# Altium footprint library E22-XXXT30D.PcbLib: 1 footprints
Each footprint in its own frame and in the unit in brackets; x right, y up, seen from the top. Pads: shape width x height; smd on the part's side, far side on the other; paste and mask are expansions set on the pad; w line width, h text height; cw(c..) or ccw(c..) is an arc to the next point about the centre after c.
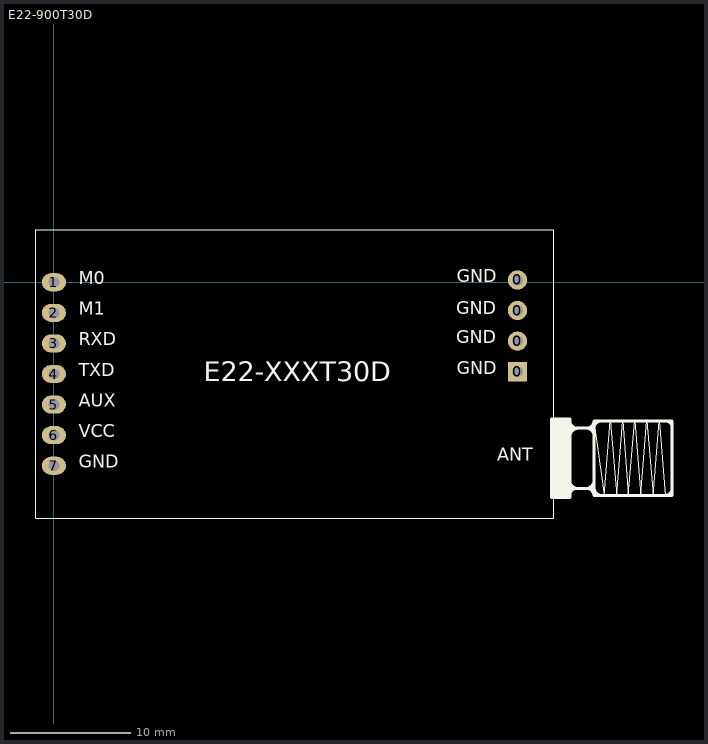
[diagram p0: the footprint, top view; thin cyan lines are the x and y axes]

## E22-900T30D [mm] "43MM*24mm-D//SMA长度12.5mm"
pads (11):
  rect 1.6x1.6 hole 0.9: 0(38.5,-7.43)
  round 1.6 hole 0.9: 0(38.5,-4.89) 0(38.5,-2.35) 0(38.5,0.19)
  oval 2x1.5 hole 0.9: 1(0,0) 2(0,-2.54) 3(0,-5.08) 4(0,-7.62) 5(0,-10.16) 6(0,-12.7) 7(0,-15.24)
Top Overlay:
  rectangle: 41.35,-17.865 42.85,-11.365
  rectangle: 41.35,-17.87 42.85,-11.37
  lines w0.1: 45.7,-17.72 44.85,-11.52 45.7,-17.72 ; 45.7,-17.72 46.22,-11.52 ; 45.7,-17.72 46.22,-11.52 ; 46.22,-11.52 46.73,-17.72 ; 46.22,-11.52 46.73,-17.72 ; 46.73,-17.72 47.24,-11.52 ; 46.73,-17.72 47.24,-11.52 ; 47.24,-11.52 47.72,-17.72 ; 47.24,-11.52 47.72,-17.72 ; 47.72,-17.72 48.24,-11.52 ; 47.72,-17.72 48.24,-11.52 ; 48.24,-11.52 48.75,-17.72 ; 48.24,-11.52 48.75,-17.72 ; 48.75,-17.72 49.24,-11.52 ; 48.75,-17.72 49.24,-11.52 ; 49.24,-11.52 49.76,-17.72 ; 49.24,-11.52 49.76,-17.72 ; 49.76,-17.72 50.28,-11.52 ; 49.76,-17.72 50.28,-11.52 ; 50.28,-11.52 50.79,-17.72 50.28,-11.52 ; -1.5,-19.62 -1.5,4.38 41.5,4.38 41.5,-19.62 -1.5,-19.62
  lines w0.254: 41.35,-17.87 41.35,-11.37 ; 41.35,-17.87 42.85,-17.87 ; 41.35,-17.87 41.35,-11.37 ; 41.35,-17.87 42.85,-17.87 ; 41.35,-11.37 42.85,-11.37 ; 41.35,-11.37 42.85,-11.37 ; 42.85,-17.87 42.85,-11.37 ; 42.85,-17.87 42.85,-11.37 ; 42.85,-16.47 ccw(c43.5,-16.47) 43.5,-17.12 ; 42.85,-16.47 ccw(c43.5,-16.47) 43.5,-17.12 ; 42.85,-16.47 42.85,-16.1 42.85,-16.47 ; 42.85,-12.82 cw(c43.55,-12.82) 43.55,-12.12 ; 42.85,-12.82 cw(c43.55,-12.82) 43.55,-12.12 ; 42.85,-12.82 42.85,-13.74 42.85,-12.82 ; 42.85,-11.49 ccw(c43.48,-11.49) 43.48,-12.12 ; 42.85,-11.49 ccw(c43.48,-11.49) 43.48,-12.12 ; 42.85,-11.49 42.85,-11.37 ; 42.85,-11.49 42.85,-11.37 ; 43.4,-17.12 ccw(c43.4,-17.67) 42.85,-17.67 cw(c43.4,-17.67) 43.4,-17.12 ; 43.4,-17.12 44.25,-17.12 ; 43.4,-17.12 44.25,-17.12 ; 43.48,-12.12 44.25,-12.12 ; 43.48,-12.12 44.25,-12.12 ; 43.5,-17.12 44.22,-17.12 ; 43.5,-17.12 44.22,-17.12 ; 43.55,-12.12 44.25,-12.12 ; 43.55,-12.12 44.25,-12.12 ; 44.22,-17.12 ccw(c44.22,-16.49) 44.85,-16.49 cw(c44.22,-16.49) 44.22,-17.12 ; 44.25,-17.12 cw(c44.25,-17.72) 44.85,-17.72 ; 44.25,-17.12 cw(c44.25,-17.72) 44.85,-17.72 ; 44.25,-12.12 ccw(c44.25,-11.52) 44.85,-11.52 ; 44.25,-12.12 cw(c44.25,-12.72) 44.85,-12.72 ccw(c44.25,-12.72) 44.25,-12.12 ; 44.25,-12.12 ccw(c44.25,-11.52) 44.85,-11.52 ; 44.85,-17.72 51.35,-17.72 ; 44.85,-17.72 44.85,-11.52 ; 44.85,-17.72 51.35,-17.72 ; 44.85,-17.72 44.85,-11.52 ; 44.85,-11.52 51.35,-11.52 ; 44.85,-11.52 51.35,-11.52 ; 45.53,-17.72 cw(c45.53,-17.04) 44.85,-17.04 ccw(c45.53,-17.04) 45.53,-17.72 ; 45.53,-17.72 45.68,-17.72 45.53,-17.72 ; 50.73,-17.72 ccw(c50.73,-17.1) 51.35,-17.1 cw(c50.73,-17.1) 50.73,-17.72 ; 50.73,-17.72 50.5,-17.72 50.73,-17.72 ; 50.81,-11.52 cw(c50.81,-12.06) 51.35,-12.06 ccw(c50.81,-12.06) 50.81,-11.52 ; 50.81,-11.52 50.41,-11.52 50.81,-11.52 ; 51.35,-17.72 51.35,-11.52 ; 51.35,-17.72 51.35,-11.52 ; 42.68,-17.12 44.85,-17.12 42.68,-17.12 ; 42.85,-12.12 44.85,-12.12 42.85,-12.12 ; 44.85,-12.13 cw(c45.46,-12.13) 45.46,-11.52 ccw(c45.46,-12.13) 44.85,-12.13
  text "GND" at 33.457,-8.001 h1.8
  text "GND" at 33.457,-0.381 h1.8
  text "GND" at 33.426,-3.016 h1.8
  text "GND" at 33.426,-5.429 h1.8
  text "GND" at 2.063,-15.78 h1.8
  text "VCC" at 2.063,-13.24 h1.8
  text "AUX" at 2.063,-10.7 h1.8
  text "TXD" at 2.063,-8.16 h1.8
  text "RXD" at 2.063,-5.62 h1.8
  text "M1" at 2.063,-3.08 h1.8
  text "M0" at 2.063,-0.54 h1.8
  text "ANT" at 36.83,-15.19 h1.8
  text "E22-XXXT30D" at 12.446,-8.763 h2.8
